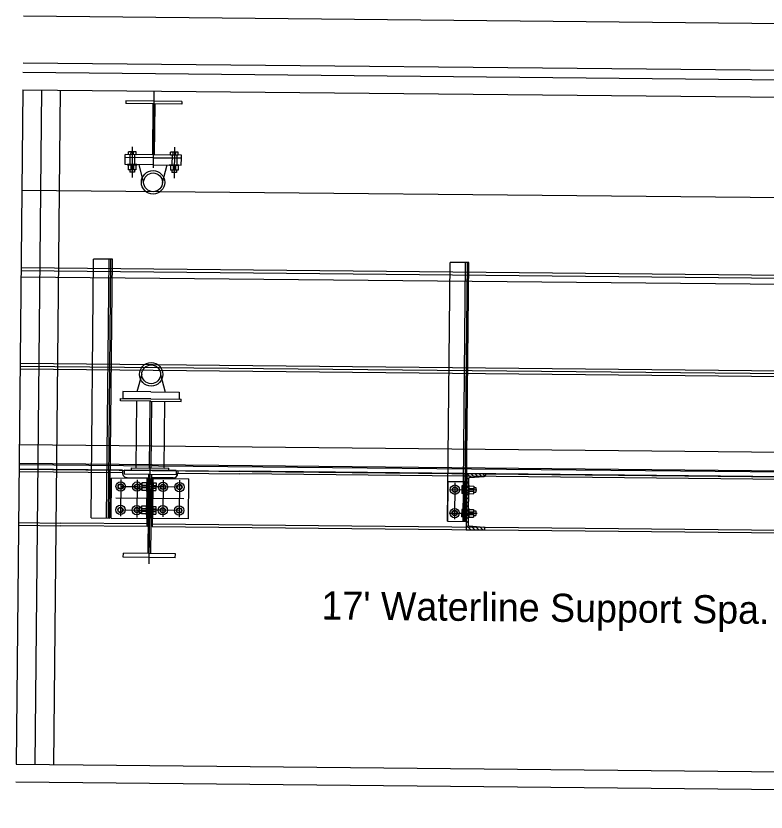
# Model space of a CAD drawing. Extents: x 632312 to 632885, y 378199 to 378534.
# Drawn here: x 632798.64 to 632811.98, y 378357.64 to 378371.81 of the extents above; entities that cross this region are included whole.
import ezdxf

# ---------------------------------------------------------------- set-up
doc = ezdxf.new("R2010")
doc.units = 0
doc.layers.add('SHT_Dimensions', color=7, linetype='Continuous')

msp = doc.modelspace()

# ---------------------------------------------------------------- linework, layer by layer
at = {"layer": 'SHT_Dimensions'}
for p, q in [((632798.775, 378371.807), (632853.461, 378371.263)), ((632798.767, 378370.974), (632853.347, 378370.431)), ((632798.765, 378370.807), (632853.487, 378370.263)), ((632798.762, 378370.494), (632798.643, 378358.495)), ((632798.762, 378370.494), (632853.573, 378369.949)), ((632799.095, 378370.491), (632798.976, 378358.492)), ((632799.429, 378370.488), (632799.31, 378358.488)), ((632801.095, 378370.47), (632801.082, 378369.106)), ((632801.593, 378370.287), (632800.593, 378370.297)), ((632800.593, 378370.297), (632800.593, 378370.247)), ((632801.593, 378370.287), (632801.593, 378370.237)), ((632801.593, 378370.237), (632800.593, 378370.247)), ((632801.077, 378370.242), (632801.068, 378369.334)), ((632801.109, 378370.242), (632801.1, 378369.334)), ((632800.71, 378369.477), (632800.705, 378368.93)), ((632801.46, 378369.469), (632801.455, 378368.923)), ((632800.582, 378369.164), (632800.583, 378369.289)), ((632800.583, 378369.289), (632800.584, 378369.339)), ((632801.083, 378369.284), (632800.583, 378369.289)), ((632801.583, 378369.279), (632800.583, 378369.289)), ((632801.584, 378369.329), (632800.584, 378369.339)), ((632800.641, 378369.339), (632800.642, 378369.391)), ((632800.777, 378369.337), (632800.641, 378369.339)), ((632800.777, 378369.389), (632800.642, 378369.391)), ((632800.667, 378369.338), (632800.666, 378369.163)), ((632800.686, 378369.338), (632800.687, 378369.39)), ((632800.732, 378369.338), (632800.732, 378369.39)), ((632800.751, 378369.338), (632800.749, 378369.162)), ((632800.777, 378369.337), (632800.777, 378369.389)), ((632801.083, 378369.284), (632801.583, 378369.279)), ((632801.391, 378369.331), (632801.392, 378369.383)), ((632801.527, 378369.33), (632801.391, 378369.331)), ((632801.527, 378369.382), (632801.392, 378369.383)), ((632801.417, 378369.331), (632801.415, 378369.155)), ((632801.436, 378369.331), (632801.437, 378369.383)), ((632801.481, 378369.33), (632801.482, 378369.382)), ((632801.501, 378369.33), (632801.499, 378369.155)), ((632801.527, 378369.33), (632801.527, 378369.382)), ((632801.582, 378369.154), (632801.583, 378369.279)), ((632801.583, 378369.279), (632801.584, 378369.329)), ((632801.082, 378369.159), (632800.582, 378369.164)), ((632800.624, 378369.163), (632800.624, 378369.153)), ((632800.791, 378369.162), (632800.624, 378369.163)), ((632800.79, 378369.151), (632800.624, 378369.153)), ((632800.639, 378369.153), (632800.639, 378369.069)), ((632800.685, 378369.152), (632800.684, 378369.069)), ((632800.73, 378369.152), (632800.729, 378369.069)), ((632800.775, 378369.151), (632800.774, 378369.068)), ((632800.791, 378369.162), (632800.79, 378369.151)), ((632800.912, 378368.848), (632800.832, 378369.161)), ((632801.082, 378369.159), (632801.582, 378369.154)), ((632801.246, 378368.845), (632801.332, 378369.156)), ((632801.374, 378369.156), (632801.374, 378369.145)), ((632801.54, 378369.154), (632801.374, 378369.156)), ((632801.54, 378369.144), (632801.374, 378369.145)), ((632801.389, 378369.145), (632801.389, 378369.062)), ((632801.434, 378369.145), (632801.434, 378369.062)), ((632801.48, 378369.144), (632801.479, 378369.061)), ((632801.525, 378369.144), (632801.524, 378369.061)), ((632801.54, 378369.154), (632801.54, 378369.144)), ((632800.774, 378369.068), (632800.639, 378369.069)), ((632800.665, 378369.069), (632800.664, 378369.028)), ((632800.748, 378369.027), (632800.664, 378369.028)), ((632800.748, 378369.068), (632800.748, 378369.027)), ((632801.524, 378369.061), (632801.389, 378369.062)), ((632801.415, 378369.062), (632801.414, 378369.02)), ((632801.497, 378369.019), (632801.414, 378369.02)), ((632801.498, 378369.061), (632801.497, 378369.019)), ((632853.591, 378368.158), (632798.745, 378368.703)), ((632799.977, 378362.878), (632800.022, 378367.482)), ((632800.356, 378367.478), (632800.022, 378367.482)), ((632800.253, 378362.875), (632800.298, 378367.479)), ((632800.284, 378362.875), (632800.33, 378367.479)), ((632800.31, 378362.874), (632800.356, 378367.478)), ((632798.731, 378367.328), (632853.151, 378366.787)), ((632806.317, 378362.817), (632806.363, 378367.421)), ((632806.696, 378367.418), (632806.363, 378367.421)), ((632806.593, 378362.814), (632806.639, 378367.418)), ((632806.625, 378362.814), (632806.67, 378367.418)), ((632806.651, 378362.814), (632806.696, 378367.418)), ((632853.788, 378366.614), (632798.729, 378367.161)), ((632798.73, 378367.276), (632853.171, 378366.735)), ((632853, 378365.08), (632798.714, 378365.62)), ((632798.713, 378365.578), (632853.075, 378365.037)), ((632798.713, 378365.526), (632853.08, 378364.985)), ((632800.878, 378365.431), (632800.792, 378365.12)), ((632801.212, 378365.428), (632801.292, 378365.115)), ((632800.542, 378365.122), (632800.541, 378364.997)), ((632801.042, 378365.117), (632800.542, 378365.122)), ((632801.042, 378365.117), (632801.542, 378365.112)), ((632801.542, 378365.112), (632801.541, 378364.987)), ((632800.499, 378364.956), (632800.499, 378364.998)), ((632800.499, 378364.998), (632801.582, 378364.987)), ((632801.04, 378364.951), (632800.499, 378364.956)), ((632801.041, 378364.992), (632800.541, 378364.997)), ((632800.779, 378363.766), (632800.79, 378364.953)), ((632801.016, 378363.763), (632801.028, 378364.951)), ((632801.04, 378364.951), (632801.582, 378364.945)), ((632801.041, 378364.992), (632801.541, 378364.987)), ((632801.053, 378364.951), (632801.041, 378363.763)), ((632801.279, 378363.761), (632801.29, 378364.948)), ((632801.582, 378364.945), (632801.582, 378364.987)), ((632798.7, 378364.182), (632852.946, 378363.643)), ((632798.696, 378363.849), (632852.942, 378363.31)), ((632798.696, 378363.828), (632852.942, 378363.289)), ((632800.695, 378363.725), (632800.695, 378363.766)), ((632800.695, 378363.766), (632801.362, 378363.76)), ((632800.779, 378363.766), (632801.279, 378363.761)), ((632801.012, 378362.059), (632801.029, 378363.773)), ((632801.361, 378363.718), (632801.362, 378363.76)), ((632798.695, 378363.745), (632849.026, 378363.244)), ((632800.534, 378363.726), (632798.695, 378363.745)), ((632800.534, 378363.679), (632798.695, 378363.697)), ((632800.534, 378363.726), (632800.534, 378363.679)), ((632800.566, 378363.726), (632800.565, 378363.654)), ((632801.49, 378363.644), (632800.565, 378363.654)), ((632801.491, 378363.717), (632800.566, 378363.726)), ((632800.991, 378362.244), (632801.005, 378363.649)), ((632801.05, 378363.649), (632801.036, 378362.244)), ((632801.491, 378363.717), (632801.49, 378363.644)), ((632801.522, 378363.717), (632801.521, 378363.669)), ((632801.521, 378363.669), (632802.625, 378363.658)), ((632801.522, 378363.717), (632802.608, 378363.706)), ((632817.534, 378363.557), (632802.608, 378363.706)), ((632817.533, 378363.51), (632802.625, 378363.658)), ((632806.659, 378363.666), (632806.649, 378362.666)), ((632806.659, 378363.666), (632806.992, 378363.662)), ((632806.728, 378363.598), (632806.662, 378363.666)), ((632806.695, 378363.665), (632806.695, 378363.664)), ((632806.71, 378363.596), (632806.971, 378363.615)), ((632806.794, 378363.602), (632806.732, 378363.665)), ((632806.859, 378363.607), (632806.803, 378363.664)), ((632806.925, 378363.611), (632806.874, 378363.663)), ((632806.986, 378363.62), (632806.944, 378363.663)), ((632806.992, 378363.662), (632806.992, 378363.635)), ((632800.331, 378362.874), (632800.338, 378363.583)), ((632801.004, 378363.576), (632800.338, 378363.583)), ((632800.504, 378363.558), (632800.498, 378362.904)), ((632800.616, 378363.594), (632800.984, 378363.591)), ((632800.796, 378363.555), (632800.789, 378362.884)), ((632800.837, 378363.473), (632800.836, 378363.39)), ((632800.878, 378363.473), (632800.837, 378363.473)), ((632800.879, 378363.499), (632800.877, 378363.364)), ((632800.962, 378363.498), (632800.879, 378363.499)), ((632800.962, 378363.514), (632800.96, 378363.347)), ((632800.973, 378363.514), (632800.962, 378363.514)), ((632800.966, 378362.868), (632800.973, 378363.576)), ((632800.973, 378363.514), (632800.971, 378363.347)), ((632801.079, 378363.471), (632800.972, 378363.472)), ((632800.975, 378362.722), (632800.984, 378363.591)), ((632800.997, 378362.868), (632801.004, 378363.576)), ((632801.042, 378362.867), (632801.049, 378363.575)), ((632801.049, 378363.575), (632801.716, 378363.569)), ((632801.07, 378363.59), (632801.061, 378362.721)), ((632801.437, 378363.586), (632801.07, 378363.59)), ((632801.073, 378362.867), (632801.08, 378363.575)), ((632801.079, 378363.497), (632801.078, 378363.362)), ((632801.079, 378363.497), (632801.132, 378363.497)), ((632801.132, 378363.497), (632801.13, 378363.361)), ((632801.257, 378363.55), (632801.251, 378362.894)), ((632801.549, 378363.547), (632801.542, 378362.888)), ((632801.709, 378362.861), (632801.716, 378363.569)), ((632806.324, 378363.525), (632806.317, 378362.817)), ((632806.324, 378363.525), (632806.658, 378363.522)), ((632806.449, 378363.501), (632806.443, 378362.853)), ((632806.619, 378362.814), (632806.626, 378363.522)), ((632806.651, 378362.814), (632806.658, 378363.522)), ((632806.689, 378363.566), (632806.658, 378363.597)), ((632806.688, 378363.495), (632806.658, 378363.527)), ((632806.689, 378363.576), (632806.681, 378362.755)), ((632800.503, 378363.435), (632800.795, 378363.432)), ((632800.795, 378363.432), (632801.025, 378363.43)), ((632800.878, 378363.39), (632800.836, 378363.39)), ((632800.961, 378363.363), (632800.877, 378363.364)), ((632800.961, 378363.453), (632800.878, 378363.454)), ((632800.961, 378363.408), (632800.878, 378363.409)), ((632800.971, 378363.347), (632800.96, 378363.347)), ((632801.078, 378363.388), (632800.971, 378363.389)), ((632801.256, 378363.428), (632801.025, 378363.43)), ((632801.078, 378363.362), (632801.13, 378363.361)), ((632801.079, 378363.452), (632801.131, 378363.451)), ((632801.079, 378363.407), (632801.131, 378363.406)), ((632801.548, 378363.425), (632801.256, 378363.428)), ((632806.365, 378363.379), (632806.839, 378363.374)), ((632806.574, 378363.445), (632806.572, 378363.309)), ((632806.625, 378363.399), (632806.573, 378363.4)), ((632806.625, 378363.354), (632806.573, 378363.355)), ((632806.626, 378363.444), (632806.574, 378363.445)), ((632806.626, 378363.444), (632806.624, 378363.309)), ((632806.625, 378363.418), (632806.687, 378363.418)), ((632806.625, 378363.335), (632806.687, 378363.334)), ((632806.687, 378363.354), (632806.656, 378363.385)), ((632806.688, 378363.425), (632806.657, 378363.456)), ((632806.688, 378363.459), (632806.686, 378363.293)), ((632806.688, 378363.459), (632806.698, 378363.459)), ((632806.698, 378363.459), (632806.697, 378363.293)), ((632806.697, 378363.353), (632806.781, 378363.352)), ((632806.698, 378363.444), (632806.782, 378363.443)), ((632806.698, 378363.398), (632806.781, 378363.398)), ((632806.782, 378363.443), (632806.78, 378363.307)), ((632806.78, 378363.333), (632806.822, 378363.333)), ((632806.781, 378363.417), (632806.823, 378363.416)), ((632806.823, 378363.416), (632806.822, 378363.333)), ((632801.629, 378363.216), (632800.418, 378363.228)), ((632806.624, 378363.309), (632806.572, 378363.309)), ((632806.685, 378363.213), (632806.655, 378363.244)), ((632806.686, 378363.283), (632806.656, 378363.314)), ((632806.686, 378363.293), (632806.697, 378363.293)), ((632806.697, 378363.308), (632806.78, 378363.307)), ((632800.833, 378363.057), (632800.832, 378362.973)), ((632800.874, 378363.056), (632800.833, 378363.057)), ((632800.874, 378363.082), (632800.873, 378362.947)), ((632800.958, 378363.082), (632800.874, 378363.082)), ((632800.958, 378363.097), (632800.956, 378362.931)), ((632800.968, 378363.097), (632800.958, 378363.097)), ((632800.968, 378363.097), (632800.967, 378362.93)), ((632801.075, 378363.054), (632800.968, 378363.055)), ((632801.075, 378363.08), (632801.074, 378362.945)), ((632801.075, 378363.08), (632801.127, 378363.08)), ((632801.127, 378363.08), (632801.126, 378362.944)), ((632806.685, 378363.142), (632806.654, 378363.173)), ((632806.684, 378363.071), (632806.654, 378363.102)), ((632806.684, 378363.043), (632806.682, 378362.876)), ((632806.684, 378363.043), (632806.694, 378363.043)), ((632806.694, 378363.043), (632806.693, 378362.876)), ((632800.499, 378363.018), (632800.79, 378363.016)), ((632800.79, 378363.016), (632801.021, 378363.013)), ((632800.873, 378362.973), (632800.832, 378362.973)), ((632800.956, 378362.946), (632800.873, 378362.947)), ((632800.957, 378363.036), (632800.874, 378363.037)), ((632800.957, 378362.991), (632800.874, 378362.992)), ((632800.967, 378362.93), (632800.956, 378362.931)), ((632801.074, 378362.971), (632800.967, 378362.972)), ((632801.252, 378363.011), (632801.021, 378363.013)), ((632801.074, 378362.99), (632801.126, 378362.99)), ((632801.074, 378362.945), (632801.126, 378362.944)), ((632801.075, 378363.035), (632801.127, 378363.035)), ((632801.543, 378363.008), (632801.252, 378363.011)), ((632806.36, 378362.963), (632806.842, 378362.958)), ((632806.569, 378363.028), (632806.568, 378362.893)), ((632806.622, 378363.028), (632806.569, 378363.028)), ((632806.621, 378362.982), (632806.569, 378362.983)), ((632806.621, 378362.937), (632806.569, 378362.938)), ((632806.622, 378363.028), (632806.62, 378362.892)), ((632806.62, 378362.918), (632806.683, 378362.918)), ((632806.621, 378363.002), (632806.683, 378363.001)), ((632806.683, 378362.93), (632806.652, 378362.961)), ((632806.683, 378363), (632806.653, 378363.032)), ((632806.693, 378362.937), (632806.776, 378362.936)), ((632806.694, 378363.027), (632806.777, 378363.026)), ((632806.694, 378362.982), (632806.777, 378362.981)), ((632806.777, 378363.026), (632806.776, 378362.891)), ((632806.776, 378362.917), (632806.818, 378362.916)), ((632806.777, 378363), (632806.819, 378363)), ((632806.819, 378363), (632806.818, 378362.916)), ((632798.686, 378362.793), (632799.438, 378362.785)), ((632800.975, 378362.77), (632799.438, 378362.785)), ((632799.977, 378362.878), (632800.31, 378362.874)), ((632800.331, 378362.874), (632800.997, 378362.868)), ((632801.709, 378362.861), (632801.042, 378362.867)), ((632801.062, 378362.769), (632816.437, 378362.616)), ((632806.317, 378362.817), (632806.651, 378362.814)), ((632806.317, 378362.817), (632806.651, 378362.814)), ((632806.62, 378362.892), (632806.568, 378362.893)), ((632806.682, 378362.859), (632806.651, 378362.89)), ((632806.681, 378362.788), (632806.651, 378362.82)), ((632806.682, 378362.876), (632806.693, 378362.876)), ((632806.693, 378362.891), (632806.776, 378362.891)), ((632798.685, 378362.745), (632799.437, 378362.737)), ((632800.975, 378362.722), (632799.437, 378362.737)), ((632801.061, 378362.721), (632816.436, 378362.568)), ((632806.662, 378362.665), (632806.649, 378362.678)), ((632806.652, 378362.666), (632806.649, 378362.669)), ((632806.649, 378362.666), (632806.983, 378362.662)), ((632806.649, 378362.666), (632806.982, 378362.662)), ((632806.732, 378362.665), (632806.65, 378362.749)), ((632806.702, 378362.734), (632806.962, 378362.71)), ((632806.803, 378362.664), (632806.738, 378362.731)), ((632806.874, 378362.663), (632806.815, 378362.724)), ((632806.945, 378362.663), (632806.891, 378362.717)), ((632806.982, 378362.696), (632806.969, 378362.709)), ((632806.983, 378362.662), (632806.983, 378362.689)), ((632800.55, 378362.176), (632800.551, 378362.249)), ((632801.476, 378362.239), (632800.551, 378362.249)), ((632801.475, 378362.167), (632801.476, 378362.239)), ((632801.475, 378362.167), (632800.55, 378362.176)), ((632798.643, 378358.495), (632852.964, 378357.955)), ((632798.64, 378358.182), (632852.992, 378357.642))]:
    msp.add_line(p, q, dxfattribs=at)
for centre, radius in [((632801.079, 378368.846), 0.208), ((632801.079, 378368.846), 0.167), ((632801.045, 378365.43), 0.208), ((632801.045, 378365.43), 0.167), ((632800.503, 378363.435), 0.0833), ((632800.503, 378363.435), 0.0469), ((632800.503, 378363.435), 0.0417), ((632800.795, 378363.432), 0.0833), ((632800.795, 378363.432), 0.0469), ((632800.795, 378363.432), 0.0417), ((632801.256, 378363.428), 0.0833), ((632801.256, 378363.428), 0.0469), ((632801.256, 378363.428), 0.0417), ((632801.547, 378363.425), 0.0833), ((632801.547, 378363.425), 0.0469), ((632801.547, 378363.425), 0.0417), ((632806.448, 378363.378), 0.0833), ((632806.448, 378363.378), 0.0469), ((632806.448, 378363.378), 0.0417), ((632800.499, 378363.018), 0.0833), ((632800.499, 378363.018), 0.0469), ((632800.499, 378363.018), 0.0417), ((632800.79, 378363.016), 0.0833), ((632800.79, 378363.016), 0.0469), ((632800.79, 378363.016), 0.0417), ((632801.252, 378363.011), 0.0833), ((632801.252, 378363.011), 0.0469), ((632801.252, 378363.011), 0.0417), ((632801.543, 378363.008), 0.0833), ((632801.543, 378363.008), 0.0469), ((632801.543, 378363.008), 0.0417), ((632806.444, 378362.962), 0.0833), ((632806.444, 378362.962), 0.0469), ((632806.444, 378362.962), 0.0417)]:
    msp.add_circle(centre, radius, dxfattribs=at)
for centre, radius, start, end in [((632800.617, 378363.678), 0.0833, 179.4304, 269.4304), ((632801.438, 378363.67), 0.0833, 269.4304, 359.4304), ((632806.971, 378363.635), 0.0208, 269.4304, 359.4388), ((632806.71, 378363.575), 0.0208, 89.4304, 179.4304), ((632806.702, 378362.755), 0.0208, 179.4304, 269.4304), ((632806.962, 378362.69), 0.0208, 359.4304, 89.4304)]:
    msp.add_arc(centre, radius, start, end, dxfattribs=at)

# ---------------------------------------------------------------- texts
msp.add_text("17' Waterline Support Spa.", height=0.5, rotation=359.4304, dxfattribs=at).set_placement((632804.072, 378361.069))

doc.saveas('drawing.dxf')
